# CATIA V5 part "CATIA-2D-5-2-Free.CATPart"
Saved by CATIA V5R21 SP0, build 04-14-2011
Part number: CATIA-2D-5-2-Free
Bounding box of the stored display mesh (mm): x -58.981 to 58.981, y 0 to 0, z -58.981 to 58.981
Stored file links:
  C:\Users\Rasoul Mohammadi\Desktop\CATIA-Free\2D\CATIA-2D-5-2-Free.CATPart
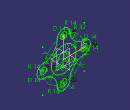
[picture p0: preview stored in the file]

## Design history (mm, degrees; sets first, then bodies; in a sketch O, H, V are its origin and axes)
Body1 (main body)
  Sketch1 on zx-plane, origin (0, 0, 0), H (-1, 0, 0), V (0, 0, 1)
    circle A1 centre (0, 0) radius 13.5
    circle A2 centre (0, 0) radius 27
    construction circle A3 centre (0, 0) radius 45
    circle A4 centre (45, 0) radius 7
    point P1 (45, 0)
    arc A5 centre (45, 0) radius 14 from (45.3011, -13.9968) to (45.3011, 13.9968) ccw
    point P2 (0, 45)
    circle A6 centre (0, 45) radius 7
    arc A7 centre (0, 45) radius 14 from (13.9968, 45.3011) to (-13.9968, 45.3011) ccw
    point P3 (-45, 0)
    circle A8 centre (-45, 0) radius 7
    arc A9 centre (-45, 0) radius 14 from (-45.3011, 13.9968) to (-45.3011, -13.9968) ccw
    point P4 (0, -45)
    circle A10 centre (0, -45) radius 7
    arc A11 centre (0, -45) radius 14 from (-13.9968, -45.3011) to (13.9968, -45.3011) ccw
    arc A12 centre (45.9894, 45.9894) radius 32 from (13.9968, 45.3011) to (45.3011, 13.9968) ccw
    arc A13 centre (-45.9894, 45.9894) radius 32 from (-45.3011, 13.9968) to (-13.9968, 45.3011) ccw
    arc A14 centre (-45.9894, -45.9894) radius 32 from (-13.9968, -45.3011) to (-45.3011, -13.9968) ccw
    arc A15 centre (45.9894, -45.9894) radius 32 from (45.3011, -13.9968) to (13.9968, -45.3011) ccw
    radius A4 = 7
    radius A3 = 45
    radius A2 = 27
    radius A5 = 14
    radius A6 = 7
    radius A7 = 14
    radius A8 = 7
    radius A9 = 14
    radius A11 = 14
    radius A10 = 7
    radius A12 = 32
    radius A1 = 13.5
    coincidence: P1 H, P1 A3, P3 A3, P4 A3, P2 A3, P2 V, P4 V, P3 H
    tangency: A12 A7, A12 A5
    fix: A15, A13, A14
